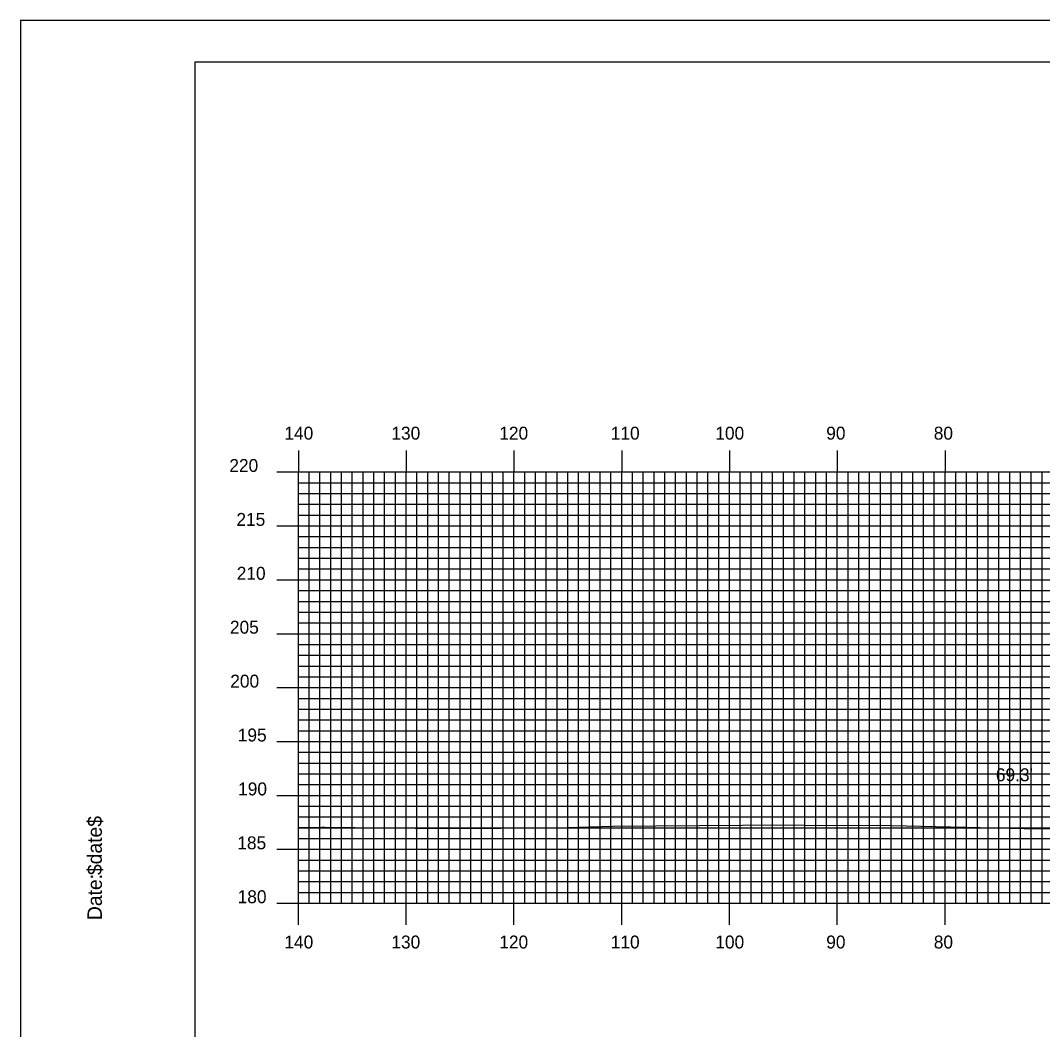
# Model space of a CAD drawing. Extents: x 1810193 to 1810536, y 442591 to 442811.
# Drawn here: x 1810193.1 to 1810287.9, y 442716.9 to 442810.5 of the extents above; entities that cross this region are included whole.
import ezdxf

# ---------------------------------------------------------------- set-up
doc = ezdxf.new("R2010")
doc.units = 0
for name, color, linetype in [('BORDER', 7, 'Continuous'), ('D_Text_Standard', 7, 'Continuous'), ('H_V ANNOTATION', 7, 'Continuous'), ('MAJOR', 7, 'Continuous'), ('MINOR', 7, 'Continuous'), ('PLOT BOUNDARY', 7, 'Continuous'), ('S_Roadway_Centerline', 7, 'Continuous')]:
    doc.layers.add(name, color=color, linetype=linetype)

msp = doc.modelspace()

# ---------------------------------------------------------------- linework, layer by layer
at = {"layer": 'BORDER'}
msp.add_lwpolyline([(1810209.263, 442596.665), (1810529.263, 442596.665), (1810529.263, 442806.665), (1810209.263, 442806.665)], close=True, dxfattribs=at)
at = {"layer": 'MAJOR'}
for p, q in [((1810218.863, 442770.669), (1810218.863, 442768.665)), ((1810228.863, 442770.669), (1810228.863, 442768.665)), ((1810238.863, 442770.669), (1810238.863, 442768.665)), ((1810248.863, 442770.669), (1810248.863, 442768.665)), ((1810258.863, 442770.669), (1810258.863, 442768.665)), ((1810268.863, 442770.669), (1810268.863, 442768.665)), ((1810278.863, 442770.669), (1810278.863, 442768.665)), ((1810216.859, 442768.665), (1810218.863, 442768.665)), ((1810218.863, 442768.665), (1810498.863, 442768.665)), ((1810218.863, 442728.665), (1810218.863, 442768.665)), ((1810218.863, 442728.665), (1810218.863, 442768.665)), ((1810218.863, 442768.665), (1810498.863, 442768.665)), ((1810228.863, 442728.665), (1810228.863, 442768.665)), ((1810238.863, 442728.665), (1810238.863, 442768.665)), ((1810248.863, 442728.665), (1810248.863, 442768.665)), ((1810258.863, 442728.665), (1810258.863, 442768.665)), ((1810268.863, 442728.665), (1810268.863, 442768.665)), ((1810278.863, 442728.665), (1810278.863, 442768.665)), ((1810216.859, 442763.665), (1810218.863, 442763.665)), ((1810218.863, 442763.665), (1810498.863, 442763.665)), ((1810216.859, 442758.665), (1810218.863, 442758.665)), ((1810218.863, 442758.665), (1810498.863, 442758.665)), ((1810216.859, 442753.665), (1810218.863, 442753.665)), ((1810218.863, 442753.665), (1810498.863, 442753.665)), ((1810216.859, 442748.665), (1810218.863, 442748.665)), ((1810218.863, 442748.665), (1810498.863, 442748.665)), ((1810216.859, 442743.665), (1810218.863, 442743.665)), ((1810218.863, 442743.665), (1810498.863, 442743.665)), ((1810216.859, 442738.665), (1810218.863, 442738.665)), ((1810218.863, 442738.665), (1810498.863, 442738.665)), ((1810216.859, 442733.665), (1810218.863, 442733.665)), ((1810218.863, 442733.665), (1810498.863, 442733.665)), ((1810216.859, 442728.665), (1810218.863, 442728.665)), ((1810218.863, 442728.665), (1810498.863, 442728.665)), ((1810218.863, 442728.665), (1810498.863, 442728.665)), ((1810218.863, 442726.661), (1810218.863, 442728.665)), ((1810228.863, 442726.661), (1810228.863, 442728.665)), ((1810238.863, 442726.661), (1810238.863, 442728.665)), ((1810248.863, 442726.661), (1810248.863, 442728.665)), ((1810258.863, 442726.661), (1810258.863, 442728.665)), ((1810268.863, 442726.661), (1810268.863, 442728.665)), ((1810278.863, 442726.661), (1810278.863, 442728.665))]:
    msp.add_line(p, q, dxfattribs=at)
at = {"layer": 'MINOR'}
for p, q in [((1810219.863, 442728.665), (1810219.863, 442768.665)), ((1810220.863, 442728.665), (1810220.863, 442768.665)), ((1810221.863, 442728.665), (1810221.863, 442768.665)), ((1810222.863, 442728.665), (1810222.863, 442768.665)), ((1810223.863, 442728.665), (1810223.863, 442768.665)), ((1810224.863, 442728.665), (1810224.863, 442768.665)), ((1810225.863, 442728.665), (1810225.863, 442768.665)), ((1810226.863, 442728.665), (1810226.863, 442768.665)), ((1810227.863, 442728.665), (1810227.863, 442768.665)), ((1810229.863, 442728.665), (1810229.863, 442768.665)), ((1810230.863, 442728.665), (1810230.863, 442768.665)), ((1810231.863, 442728.665), (1810231.863, 442768.665)), ((1810232.863, 442728.665), (1810232.863, 442768.665)), ((1810233.863, 442728.665), (1810233.863, 442768.665)), ((1810234.863, 442728.665), (1810234.863, 442768.665)), ((1810235.863, 442728.665), (1810235.863, 442768.665)), ((1810236.863, 442728.665), (1810236.863, 442768.665)), ((1810237.863, 442728.665), (1810237.863, 442768.665)), ((1810239.863, 442728.665), (1810239.863, 442768.665)), ((1810240.863, 442728.665), (1810240.863, 442768.665)), ((1810241.863, 442728.665), (1810241.863, 442768.665)), ((1810242.863, 442728.665), (1810242.863, 442768.665)), ((1810243.863, 442728.665), (1810243.863, 442768.665)), ((1810244.863, 442728.665), (1810244.863, 442768.665)), ((1810245.863, 442728.665), (1810245.863, 442768.665)), ((1810246.863, 442728.665), (1810246.863, 442768.665)), ((1810247.863, 442728.665), (1810247.863, 442768.665)), ((1810249.863, 442728.665), (1810249.863, 442768.665)), ((1810250.863, 442728.665), (1810250.863, 442768.665)), ((1810251.863, 442728.665), (1810251.863, 442768.665)), ((1810252.863, 442728.665), (1810252.863, 442768.665)), ((1810253.863, 442728.665), (1810253.863, 442768.665)), ((1810254.863, 442728.665), (1810254.863, 442768.665)), ((1810255.863, 442728.665), (1810255.863, 442768.665)), ((1810256.863, 442728.665), (1810256.863, 442768.665)), ((1810257.863, 442728.665), (1810257.863, 442768.665)), ((1810259.863, 442728.665), (1810259.863, 442768.665)), ((1810260.863, 442728.665), (1810260.863, 442768.665)), ((1810261.863, 442728.665), (1810261.863, 442768.665)), ((1810262.863, 442728.665), (1810262.863, 442768.665)), ((1810263.863, 442728.665), (1810263.863, 442768.665)), ((1810264.863, 442728.665), (1810264.863, 442768.665)), ((1810265.863, 442728.665), (1810265.863, 442768.665)), ((1810266.863, 442728.665), (1810266.863, 442768.665)), ((1810267.863, 442728.665), (1810267.863, 442768.665)), ((1810269.863, 442728.665), (1810269.863, 442768.665)), ((1810270.863, 442728.665), (1810270.863, 442768.665)), ((1810271.863, 442728.665), (1810271.863, 442768.665)), ((1810272.863, 442728.665), (1810272.863, 442768.665)), ((1810273.863, 442728.665), (1810273.863, 442768.665)), ((1810274.863, 442728.665), (1810274.863, 442768.665)), ((1810275.863, 442728.665), (1810275.863, 442768.665)), ((1810276.863, 442728.665), (1810276.863, 442768.665)), ((1810277.863, 442728.665), (1810277.863, 442768.665)), ((1810279.863, 442728.665), (1810279.863, 442768.665)), ((1810280.863, 442728.665), (1810280.863, 442768.665)), ((1810281.863, 442728.665), (1810281.863, 442768.665)), ((1810282.863, 442728.665), (1810282.863, 442768.665)), ((1810283.863, 442728.665), (1810283.863, 442768.665)), ((1810284.863, 442728.665), (1810284.863, 442768.665)), ((1810285.863, 442728.665), (1810285.863, 442768.665)), ((1810286.863, 442728.665), (1810286.863, 442768.665)), ((1810287.863, 442728.665), (1810287.863, 442768.665)), ((1810218.863, 442767.665), (1810498.863, 442767.665)), ((1810218.863, 442767.665), (1810220.867, 442767.665)), ((1810218.863, 442766.665), (1810498.863, 442766.665)), ((1810218.863, 442766.665), (1810220.867, 442766.665)), ((1810218.863, 442765.665), (1810498.863, 442765.665)), ((1810218.863, 442765.665), (1810220.867, 442765.665)), ((1810218.863, 442764.665), (1810498.863, 442764.665)), ((1810218.863, 442764.665), (1810220.867, 442764.665)), ((1810218.863, 442762.665), (1810498.863, 442762.665)), ((1810218.863, 442762.665), (1810220.867, 442762.665)), ((1810218.863, 442761.665), (1810498.863, 442761.665)), ((1810218.863, 442761.665), (1810220.867, 442761.665)), ((1810218.863, 442760.665), (1810498.863, 442760.665)), ((1810218.863, 442760.665), (1810220.867, 442760.665)), ((1810218.863, 442759.665), (1810498.863, 442759.665)), ((1810218.863, 442759.665), (1810220.867, 442759.665)), ((1810218.863, 442757.665), (1810498.863, 442757.665)), ((1810218.863, 442757.665), (1810220.867, 442757.665)), ((1810218.863, 442756.665), (1810498.863, 442756.665)), ((1810218.863, 442756.665), (1810220.867, 442756.665)), ((1810218.863, 442755.665), (1810498.863, 442755.665)), ((1810218.863, 442755.665), (1810220.867, 442755.665)), ((1810218.863, 442754.665), (1810498.863, 442754.665)), ((1810218.863, 442754.665), (1810220.867, 442754.665)), ((1810218.863, 442752.665), (1810498.863, 442752.665)), ((1810218.863, 442752.665), (1810220.867, 442752.665)), ((1810218.863, 442751.665), (1810498.863, 442751.665)), ((1810218.863, 442751.665), (1810220.867, 442751.665)), ((1810218.863, 442750.665), (1810498.863, 442750.665)), ((1810218.863, 442750.665), (1810220.867, 442750.665)), ((1810218.863, 442749.665), (1810498.863, 442749.665)), ((1810218.863, 442749.665), (1810220.867, 442749.665)), ((1810218.863, 442747.665), (1810498.863, 442747.665)), ((1810218.863, 442747.665), (1810220.867, 442747.665)), ((1810218.863, 442746.665), (1810498.863, 442746.665)), ((1810218.863, 442746.665), (1810220.867, 442746.665)), ((1810218.863, 442745.665), (1810498.863, 442745.665)), ((1810218.863, 442745.665), (1810220.867, 442745.665)), ((1810218.863, 442744.665), (1810498.863, 442744.665)), ((1810218.863, 442744.665), (1810220.867, 442744.665)), ((1810218.863, 442742.665), (1810498.863, 442742.665)), ((1810218.863, 442742.665), (1810220.867, 442742.665)), ((1810218.863, 442741.665), (1810498.863, 442741.665)), ((1810218.863, 442741.665), (1810220.867, 442741.665)), ((1810218.863, 442740.665), (1810498.863, 442740.665)), ((1810218.863, 442740.665), (1810220.867, 442740.665)), ((1810218.863, 442739.665), (1810498.863, 442739.665)), ((1810218.863, 442739.665), (1810220.867, 442739.665)), ((1810218.863, 442737.665), (1810498.863, 442737.665)), ((1810218.863, 442737.665), (1810220.867, 442737.665)), ((1810218.863, 442736.665), (1810498.863, 442736.665)), ((1810218.863, 442736.665), (1810220.867, 442736.665)), ((1810218.863, 442735.665), (1810498.863, 442735.665)), ((1810218.863, 442735.665), (1810220.867, 442735.665)), ((1810218.863, 442734.665), (1810498.863, 442734.665)), ((1810218.863, 442734.665), (1810220.867, 442734.665)), ((1810218.863, 442732.665), (1810498.863, 442732.665)), ((1810218.863, 442732.665), (1810220.867, 442732.665)), ((1810218.863, 442731.665), (1810498.863, 442731.665)), ((1810218.863, 442731.665), (1810220.867, 442731.665)), ((1810218.863, 442730.665), (1810498.863, 442730.665)), ((1810218.863, 442730.665), (1810220.867, 442730.665)), ((1810218.863, 442729.665), (1810498.863, 442729.665)), ((1810218.863, 442729.665), (1810220.867, 442729.665))]:
    msp.add_line(p, q, dxfattribs=at)
at = {"layer": 'PLOT BOUNDARY'}
msp.add_lwpolyline([(1810193.077, 442590.547), (1810533.077, 442590.547), (1810533.077, 442810.547), (1810193.077, 442810.547)], close=True, dxfattribs=at)
at = {"layer": 'S_Roadway_Centerline'}
msp.add_lwpolyline([(1810218.863, 442735.685), (1810221.023, 442735.712), (1810221.348, 442735.716), (1810232.472, 442735.587), (1810242.845, 442735.648), (1810247.999, 442735.806), (1810264.074, 442735.938), (1810267.524, 442735.861), (1810272.56, 442735.895), (1810286.214, 442735.602), (1810296.116, 442735.497), (1810307.396, 442735.531), (1810320.875, 442735.497), (1810325.928, 442735.47), (1810329.246, 442735.478), (1810346.559, 442735.523), (1810351.088, 442735.511), (1810360.465, 442735.328), (1810370.762, 442735.46), (1810371.832, 442735.462), (1810372.661, 442735.446), (1810393.273, 442735.265)], dxfattribs=at)

# ---------------------------------------------------------------- texts
at = {"layer": 'BORDER'}
for s, p in [('$date$', (1810200.633, 442731.275)), ('Date:', (1810200.633, 442727.099))]:
    msp.add_text(s, height=1.3392, rotation=90, dxfattribs=at).set_placement(p)
at = {"layer": 'D_Text_Standard'}
msp.add_text("69.3'", height=1.2, dxfattribs=at).set_placement((1810283.576, 442739.978))
at = {"layer": 'H_V ANNOTATION'}
for s, p in [('140', (1810217.568, 442771.665)), ('130', (1810227.493, 442771.665)), ('120', (1810237.504, 442771.665)), ('110', (1810247.847, 442771.665)), ('100', (1810257.547, 442771.665)), ('90', (1810267.836, 442771.665)), ('80', (1810277.814, 442771.665)), ('220', (1810212.459, 442768.665)), ('215', (1810213.113, 442763.665)), ('210', (1810213.145, 442758.665)), ('205', (1810212.513, 442753.665)), ('200', (1810212.545, 442748.665)), ('195', (1810213.241, 442743.665)), ('190', (1810213.273, 442738.665)), ('185', (1810213.198, 442733.665)), ('180', (1810213.23, 442728.665)), ('140', (1810217.568, 442724.465)), ('130', (1810227.493, 442724.465)), ('120', (1810237.504, 442724.465)), ('110', (1810247.847, 442724.465)), ('100', (1810257.547, 442724.465)), ('90', (1810267.836, 442724.465)), ('80', (1810277.814, 442724.465))]:
    msp.add_text(s, height=1.2, dxfattribs=at).set_placement(p)
at = {"layer": 'MAJOR'}
msp.add_text('-', height=0.012, dxfattribs=at).set_placement((1810218.855, 442728.665))

doc.saveas('drawing.dxf')
